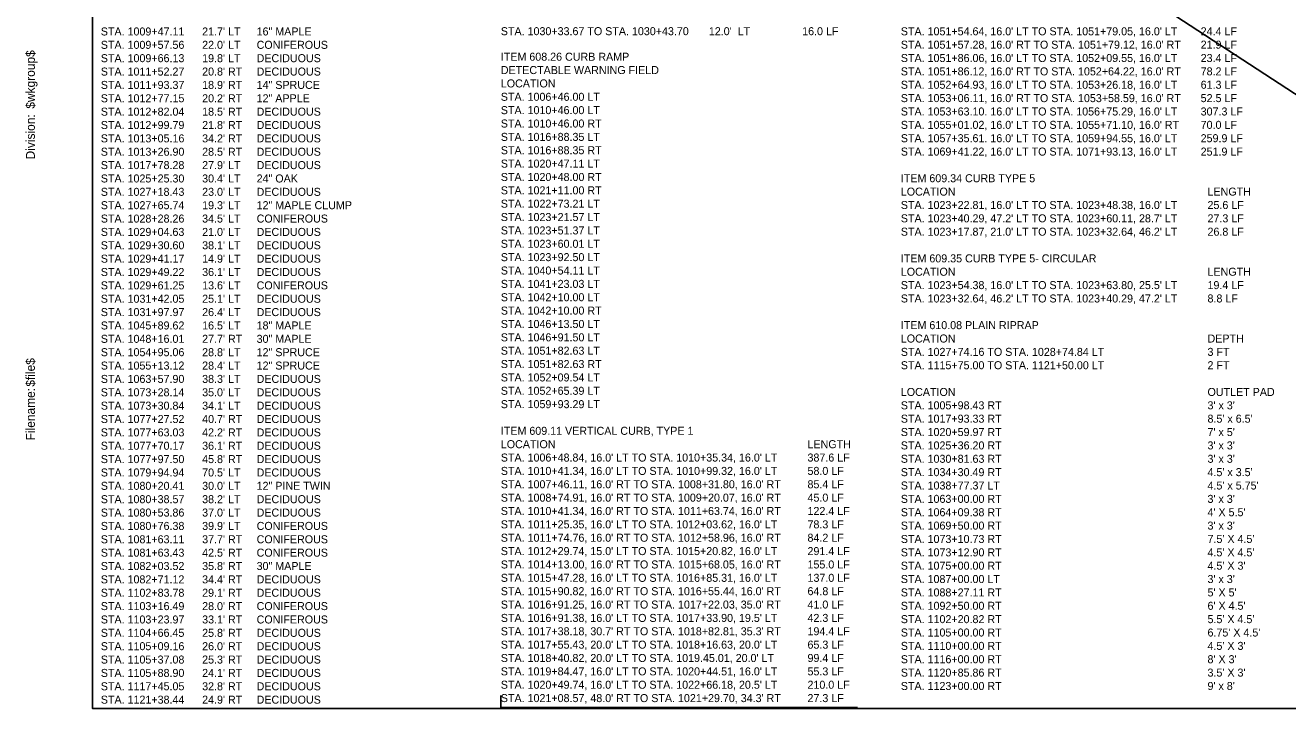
# Model space of a CAD drawing. Extents: x -831 to 3331, y -1004 to 250.
# Drawn here: x 117.9 to 591.3, y -283.3 to -19.2 of the extents above; entities that cross this region are included whole.
import ezdxf

# ---------------------------------------------------------------- set-up
doc = ezdxf.new("R2010")
doc.units = 0
doc.layers.add('BORDER', color=7, linetype='Continuous')
doc.layers.add('Default', color=7, linetype='Continuous')

msp = doc.modelspace()

# ---------------------------------------------------------------- linework, layer by layer
at = {"layer": 'BORDER'}
msp.add_lwpolyline([(143.03, 249.69), (943.03, 249.69), (943.03, -275.31), (143.03, -275.31)], close=True, dxfattribs=at)
at = {"layer": 'Default'}
msp.add_line((143.03, 249.69), (958.96, -283.29), dxfattribs=at)
msp.add_lwpolyline([(296.19, -270.51), (296.19, -274.94), (429.88, -274.94)], dxfattribs=at)

# ---------------------------------------------------------------- texts
at = {"layer": 'BORDER'}
for s, p in [('$wkgroup$', (121.46, -50.46)), ('Division:', (121.46, -69.48)), ('$file$', (121.46, -154.68)), ('Filename:', (121.46, -174.81))]:
    msp.add_text(s, height=3.348, rotation=90, dxfattribs=at).set_placement(p)
at = {"layer": 'Default'}
for s, p in [('STA. 1009+47.11', (146.19, -23.01)), ("21.7' LT", (184.19, -23.01)), ('16" MAPLE', (204.62, -23.01)), ('STA. 1030+33.67 TO STA. 1030+43.70', (296.19, -22.91)), ("12.0'  LT", (374.19, -22.91)), ('16.0 LF', (409.19, -22.91)), ("STA. 1051+54.64, 16.0' LT TO STA. 1051+79.05, 16.0' LT", (446.19, -22.95)), ('24.4 LF', (558.62, -22.95)), ('STA. 1009+57.56', (146.19, -28.02)), ("22.0' LT", (184.19, -28.02)), ('CONIFEROUS', (204.62, -28.02)), ("STA. 1051+57.28, 16.0' RT TO STA. 1051+79.12, 16.0' RT", (446.19, -27.96)), ('21.9 LF', (558.62, -27.96)), ('STA. 1009+66.13', (146.19, -33.03)), ("19.8' LT", (184.19, -33.03)), ('DECIDUOUS', (204.62, -33.03)), ('ITEM 608.26 CURB RAMP ', (296.19, -32.48)), ("STA. 1051+86.06, 16.0' LT TO STA. 1052+09.55, 16.0' LT", (446.19, -32.97)), ('23.4 LF', (558.62, -32.97)), ('STA. 1011+52.27', (146.19, -38.04)), ("20.8' RT", (184.19, -38.04)), ('DECIDUOUS', (204.62, -38.04)), ('DETECTABLE WARNING FIELD', (296.19, -37.48)), ("STA. 1051+86.12, 16.0' RT TO STA. 1052+64.22, 16.0' RT", (446.19, -37.98)), ('78.2 LF', (558.62, -37.98)), ('STA. 1011+93.37', (146.19, -43.05)), ("18.9' RT", (184.19, -43.05)), ('14" SPRUCE', (204.62, -43.05)), ('LOCATION', (296.19, -42.49)), ("STA. 1052+64.93, 16.0' LT TO STA. 1053+26.18, 16.0' LT", (446.19, -42.99)), ('61.3 LF', (558.62, -42.99)), ('STA. 1012+77.15', (146.19, -48.06)), ("20.2' RT", (184.19, -48.06)), ('12" APPLE', (204.62, -48.06)), ('STA. 1006+46.00 LT', (296.19, -47.5)), ("STA. 1053+06.11, 16.0' RT TO STA. 1053+58.59, 16.0' RT", (446.19, -48)), ('52.5 LF', (558.62, -48)), ('STA. 1012+82.04', (146.19, -53.07)), ("18.5' RT", (184.19, -53.07)), ('DECIDUOUS', (204.62, -53.07)), ('STA. 1010+46.00 LT', (296.19, -52.51)), ("STA. 1053+63.10. 16.0' LT TO STA. 1056+75.29, 16.0' LT", (446.19, -53.01)), ('307.3 LF', (558.62, -53.01)), ('STA. 1012+99.79', (146.19, -58.08)), ("21.8' RT", (184.19, -58.08)), ('DECIDUOUS', (204.62, -58.08)), ('STA. 1010+46.00 RT', (296.19, -57.52)), ("STA. 1055+01.02, 16.0' LT TO STA. 1055+71.10, 16.0' RT", (446.19, -58.02)), ('70.0 LF', (558.62, -58.02)), ('STA. 1013+05.16', (146.19, -63.09)), ("34.2' RT", (184.19, -63.09)), ('DECIDUOUS', (204.62, -63.09)), ('STA. 1016+88.35 LT', (296.19, -62.53)), ("STA. 1057+35.61. 16.0' LT TO STA. 1059+94.55, 16.0' LT", (446.19, -63.03)), ('259.9 LF', (558.62, -63.03)), ('STA. 1013+26.90', (146.19, -68.1)), ("28.5' RT", (184.19, -68.1)), ('DECIDUOUS', (204.62, -68.1)), ('STA. 1016+88.35 RT', (296.19, -67.54)), ("STA. 1069+41.22, 16.0' LT TO STA. 1071+93.13, 16.0' LT", (446.19, -68.04)), ('251.9 LF', (558.62, -68.04)), ('STA. 1017+78.28', (146.19, -73.11)), ("27.9' LT", (184.19, -73.11)), ('DECIDUOUS', (204.62, -73.11)), ('STA. 1020+47.11 LT', (296.19, -72.55)), ('STA. 1025+25.30', (146.19, -78.12)), ("30.4' LT", (184.19, -78.12)), ('24" OAK', (204.62, -78.12)), ('STA. 1020+48.00 RT', (296.19, -77.56)), ('ITEM 609.34 CURB TYPE 5', (446.19, -78.04)), ('STA. 1027+18.43', (146.19, -83.13)), ("23.0' LT", (184.19, -83.13)), ('DECIDUOUS', (204.62, -83.13)), ('STA. 1021+11.00 RT', (296.19, -82.57)), ('LOCATION', (446.19, -83.05)), ('LENGTH', (561.19, -83.05)), ('STA. 1027+65.74', (146.19, -88.14)), ("19.3' LT", (184.19, -88.14)), ('12" MAPLE CLUMP', (204.62, -88.14)), ('STA. 1022+73.21 LT', (296.19, -87.58)), ("STA. 1023+22.81, 16.0' LT TO STA. 1023+48.38, 16.0' LT", (446.19, -88.06)), ('25.6 LF', (561.19, -88.06)), ('STA. 1023+21.57 LT', (296.19, -92.59)), ('STA. 1028+28.26', (146.19, -93.15)), ("34.5' LT", (184.19, -93.15)), ('CONIFEROUS', (204.62, -93.15)), ('STA. 1023+51.37 LT', (296.19, -97.6)), ("STA. 1023+40.29, 47.2' LT TO STA. 1023+60.11, 28.7' LT", (446.19, -93.07)), ('27.3 LF', (561.19, -93.07)), ('STA. 1029+04.63', (146.19, -98.16)), ("21.0' LT", (184.19, -98.16)), ('DECIDUOUS', (204.62, -98.16)), ("STA. 1023+17.87, 21.0' LT TO STA. 1023+32.64, 46.2' LT", (446.19, -98.08)), ('26.8 LF', (561.19, -98.08)), ('STA. 1029+30.60', (146.19, -103.17)), ("38.1' LT", (184.19, -103.17)), ('DECIDUOUS', (204.62, -103.17)), ('STA. 1023+60.01 LT', (296.19, -102.61)), ('STA. 1029+41.17', (146.19, -108.18)), ("14.9' LT", (184.19, -108.18)), ('DECIDUOUS', (204.62, -108.18)), ('STA. 1023+92.50 LT', (296.19, -107.62)), ('ITEM 609.35 CURB TYPE 5- CIRCULAR', (446.19, -108.08)), ('STA. 1029+49.22', (146.19, -113.19)), ("36.1' LT", (184.19, -113.19)), ('DECIDUOUS', (204.62, -113.19)), ('STA. 1040+54.11 LT', (296.19, -112.63)), ('LOCATION', (446.19, -113.09)), ('LENGTH', (561.19, -113.09)), ('STA. 1029+61.25', (146.19, -118.2)), ("13.6' LT", (184.19, -118.2)), ('CONIFEROUS', (204.62, -118.2)), ('STA. 1041+23.03 LT', (296.19, -117.64)), ("STA. 1023+54.38, 16.0' LT TO STA. 1023+63.80, 25.5' LT", (446.19, -118.1)), ('19.4 LF', (561.19, -118.1)), ('STA. 1031+42.05', (146.19, -123.21)), ("25.1' LT", (184.19, -123.21)), ('DECIDUOUS', (204.62, -123.21)), ('STA. 1042+10.00 LT', (296.19, -122.65)), ("STA. 1023+32.64, 46.2' LT TO STA. 1023+40.29, 47.2' LT", (446.19, -123.11)), ('8.8 LF', (561.19, -123.11)), ('STA. 1031+97.97', (146.19, -128.22)), ("26.4' LT", (184.19, -128.22)), ('DECIDUOUS', (204.62, -128.22)), ('STA. 1042+10.00 RT', (296.19, -127.66)), ('STA. 1045+89.62', (146.19, -133.23)), ("16.5' LT", (184.19, -133.23)), ('18" MAPLE', (204.62, -133.23)), ('STA. 1046+13.50 LT', (296.19, -132.67)), ('ITEM 610.08 PLAIN RIPRAP', (446.19, -133.11)), ('STA. 1048+16.01', (146.19, -138.24)), ("27.7' RT", (184.19, -138.24)), ('30" MAPLE', (204.62, -138.24)), ('STA. 1046+91.50 LT', (296.19, -137.68)), ('LOCATION', (446.19, -138.12)), ('DEPTH', (561.19, -138.12)), ('STA. 1054+95.06', (146.19, -143.25)), ("28.8' LT", (184.19, -143.25)), ('12" SPRUCE', (204.62, -143.25)), ('STA. 1051+82.63 LT', (296.19, -142.69)), ('STA. 1027+74.16 TO STA. 1028+74.84 LT', (446.19, -143.13)), ('3 FT', (561.19, -143.13)), ('STA. 1055+13.12', (146.19, -148.26)), ("28.4' LT", (184.19, -148.26)), ('12" SPRUCE', (204.62, -148.26)), ('STA. 1051+82.63 RT', (296.19, -147.7)), ('STA. 1115+75.00 TO STA. 1121+50.00 LT', (446.19, -148.14)), ('2 FT', (561.19, -148.14)), ('STA. 1063+57.90', (146.19, -153.27)), ("38.3' LT", (184.19, -153.27)), ('DECIDUOUS', (204.62, -153.27)), ('STA. 1052+09.54 LT', (296.19, -152.71)), ('STA. 1073+28.14', (146.19, -158.28)), ("35.0' LT", (184.19, -158.28)), ('DECIDUOUS', (204.62, -158.28)), ('STA. 1052+65.39 LT', (296.19, -157.72)), ('LOCATION', (446.19, -158.16)), ('OUTLET PAD', (561.19, -158.16)), ('STA. 1073+30.84', (146.19, -163.29)), ("34.1' LT", (184.19, -163.29)), ('DECIDUOUS', (204.62, -163.29)), ('STA. 1059+93.29 LT', (296.19, -162.73)), ('STA. 1005+98.43 RT', (446.19, -163.17)), ("3' x 3'", (561.19, -163.17)), ('STA. 1077+27.52', (146.19, -168.3)), ("40.7' RT", (184.19, -168.3)), ('DECIDUOUS', (204.62, -168.3)), ('STA. 1017+93.33 RT', (446.19, -168.18)), ("8.5' x 6.5'", (561.19, -168.18)), ('STA. 1077+63.03', (146.19, -173.31)), ("42.2' RT", (184.19, -173.31)), ('DECIDUOUS', (204.62, -173.31)), ('ITEM 609.11 VERTICAL CURB, TYPE 1', (296.19, -172.73)), ('STA. 1020+59.97 RT', (446.19, -173.19)), ("7' x 5'", (561.19, -173.19)), ('LOCATION', (296.19, -177.74)), ('LENGTH', (411.19, -177.74)), ('STA. 1025+36.20 RT', (446.19, -178.2)), ("3' x 3'", (561.19, -178.2)), ('STA. 1077+70.17', (146.19, -178.32)), ("36.1' RT", (184.19, -178.32)), ('DECIDUOUS', (204.62, -178.32)), ("STA. 1006+48.84, 16.0' LT TO STA. 1010+35.34, 16.0' LT", (296.19, -182.75)), ('387.6 LF', (411.19, -182.75)), ('STA. 1077+97.50', (146.19, -183.33)), ("45.8' RT", (184.19, -183.33)), ('DECIDUOUS', (204.62, -183.33)), ('STA. 1030+81.63 RT', (446.19, -183.21)), ("3' x 3'", (561.19, -183.21)), ('STA. 1079+94.94', (146.19, -188.34)), ("70.5' LT", (184.19, -188.34)), ('DECIDUOUS', (204.62, -188.34)), ("STA. 1010+41.34, 16.0' LT TO STA. 1010+99.32, 16.0' LT", (296.19, -187.76)), ('58.0 LF', (411.19, -187.76)), ('STA. 1034+30.49 RT', (446.19, -188.22)), ("4.5' x 3.5'", (561.19, -188.22)), ('STA. 1080+20.41', (146.19, -193.35)), ("30.0' LT", (184.19, -193.35)), ('12" PINE TWIN', (204.62, -193.35)), ("STA. 1007+46.11, 16.0' RT TO STA. 1008+31.80, 16.0' RT", (296.19, -192.77)), ('85.4 LF', (411.19, -192.77)), ('STA. 1038+77.37 LT', (446.19, -193.23)), ("4.5' x 5.75'", (561.19, -193.23)), ('STA. 1080+38.57', (146.19, -198.36)), ("38.2' LT", (184.19, -198.36)), ('DECIDUOUS', (204.62, -198.36)), ("STA. 1008+74.91, 16.0' RT TO STA. 1009+20.07, 16.0' RT", (296.19, -197.78)), ('45.0 LF', (411.19, -197.78)), ('STA. 1063+00.00 RT', (446.19, -198.24)), ("3' x 3'", (561.19, -198.24)), ('STA. 1080+53.86', (146.19, -203.37)), ("37.0' LT", (184.19, -203.37)), ('DECIDUOUS', (204.62, -203.37)), ("STA. 1010+41.34, 16.0' RT TO STA. 1011+63.74, 16.0' RT", (296.19, -202.79)), ('122.4 LF', (411.19, -202.79)), ('STA. 1064+09.38 RT', (446.19, -203.25)), ("4' X 5.5'", (561.19, -203.25)), ('STA. 1080+76.38', (146.19, -208.38)), ("39.9' LT", (184.19, -208.38)), ('CONIFEROUS', (204.62, -208.38)), ("STA. 1011+25.35, 16.0' LT TO STA. 1012+03.62, 16.0' LT ", (296.19, -207.8)), ('78.3 LF', (411.19, -207.8)), ('STA. 1069+50.00 RT', (446.19, -208.26)), ("3' x 3'", (561.19, -208.26)), ('STA. 1081+63.11', (146.19, -213.39)), ("37.7' RT", (184.19, -213.39)), ('CONIFEROUS', (204.62, -213.39)), ("STA. 1011+74.76, 16.0' RT TO STA. 1012+58.96, 16.0' RT", (296.19, -212.81)), ('84.2 LF', (411.19, -212.81)), ('STA. 1073+10.73 RT', (446.19, -213.27)), ("7.5' X 4.5'", (561.19, -213.27)), ('STA. 1081+63.43', (146.19, -218.4)), ("42.5' RT", (184.19, -218.4)), ('CONIFEROUS', (204.62, -218.4)), ("STA. 1012+29.74, 15.0' LT TO STA. 1015+20.82, 16.0' LT", (296.19, -217.82)), ('291.4 LF', (411.19, -217.82)), ('STA. 1073+12.90 RT', (446.19, -218.28)), ("4.5' X 4.5'", (561.19, -218.28)), ('STA. 1082+03.52', (146.19, -223.41)), ("35.8' RT", (184.19, -223.41)), ('30" MAPLE', (204.62, -223.41)), ("STA. 1014+13.00, 16.0' RT TO STA. 1015+68.05, 16.0' RT", (296.19, -222.83)), ('155.0 LF', (411.19, -222.83)), ('STA. 1075+00.00 RT', (446.19, -223.29)), ("4.5' X 3'", (561.19, -223.29)), ('STA. 1082+71.12', (146.19, -228.42)), ("34.4' RT", (184.19, -228.42)), ('DECIDUOUS', (204.62, -228.42)), ("STA. 1015+47.28, 16.0' LT TO STA. 1016+85.31, 16.0' LT", (296.19, -227.84)), ('137.0 LF', (411.19, -227.84)), ('STA. 1087+00.00 LT', (446.19, -228.3)), ("3' x 3'", (561.19, -228.3)), ('STA. 1102+83.78', (146.19, -233.43)), ("29.1' RT", (184.19, -233.43)), ('DECIDUOUS', (204.62, -233.43)), ("STA. 1015+90.82, 16.0' RT TO STA. 1016+55.44, 16.0' RT", (296.19, -232.85)), ('64.8 LF', (411.19, -232.85)), ('STA. 1088+27.11 RT', (446.19, -233.31)), ("5' X 5'", (561.19, -233.31)), ('STA. 1103+16.49', (146.19, -238.44)), ("28.0' RT", (184.19, -238.44)), ('CONIFEROUS', (204.62, -238.44)), ("STA. 1016+91.25, 16.0' RT TO STA. 1017+22.03, 35.0' RT", (296.19, -237.86)), ('41.0 LF', (411.19, -237.86)), ('STA. 1092+50.00 RT', (446.19, -238.32)), ("6' X 4.5'", (561.19, -238.32)), ('STA. 1103+23.97', (146.19, -243.45)), ("33.1' RT", (184.19, -243.45)), ('CONIFEROUS', (204.62, -243.45)), ("STA. 1016+91.38, 16.0' LT TO STA. 1017+33.90, 19.5' LT", (296.19, -242.87)), ('42.3 LF', (411.19, -242.87)), ('STA. 1102+20.82 RT', (446.19, -243.33)), ("5.5' X 4.5'", (561.19, -243.33)), ('STA. 1104+66.45', (146.19, -248.46)), ("25.8' RT", (184.19, -248.46)), ('DECIDUOUS', (204.62, -248.46)), ("STA. 1017+38.18, 30.7' RT TO STA. 1018+82.81, 35.3' RT", (296.19, -247.88)), ('194.4 LF', (411.19, -247.88)), ('STA. 1105+00.00 RT', (446.19, -248.34)), ("6.75' X 4.5'", (561.19, -248.34)), ('STA. 1105+09.16', (146.19, -253.47)), ("26.0' RT", (184.19, -253.47)), ('DECIDUOUS', (204.62, -253.47)), ("STA. 1017+55.43, 20.0' LT TO STA. 1018+16.63, 20.0' LT", (296.19, -252.89)), ('65.3 LF', (411.19, -252.89)), ('STA. 1110+00.00 RT', (446.19, -253.35)), ("4.5' X 3'", (561.19, -253.35)), ('STA. 1105+37.08', (146.19, -258.48)), ("25.3' RT", (184.19, -258.48)), ('DECIDUOUS', (204.62, -258.48)), ("STA. 1018+40.82, 20.0' LT TO STA. 1019.45.01, 20.0' LT", (296.19, -257.9)), ('99.4 LF', (411.19, -257.9)), ('STA. 1116+00.00 RT', (446.19, -258.36)), ("8' X 3'", (561.19, -258.36)), ("STA. 1019+84.47, 16.0' LT TO STA. 1020+44.51, 16.0' LT", (296.19, -262.91)), ('55.3 LF', (411.19, -262.91)), ('STA. 1120+85.86 RT', (446.19, -263.37)), ("3.5' X 3'", (561.19, -263.37)), ('STA. 1105+88.90', (146.19, -263.49)), ("24.1' RT", (184.19, -263.49)), ('DECIDUOUS', (204.62, -263.49)), ("STA. 1020+49.74, 16.0' LT TO STA. 1022+66.18, 20.5' LT", (296.19, -267.92)), ('210.0 LF', (411.19, -267.92)), ('STA. 1117+45.05', (146.19, -268.5)), ("32.8' RT", (184.19, -268.5)), ('DECIDUOUS', (204.62, -268.5)), ('STA. 1123+00.00 RT', (446.19, -268.38)), ("9' x 8'", (561.19, -268.38)), ('STA. 1121+38.44', (146.19, -273.51)), ("24.9' RT", (184.19, -273.51)), ('DECIDUOUS', (204.62, -273.51)), ("STA. 1021+08.57, 48.0' RT TO STA. 1021+29.70, 34.3' RT", (296.19, -272.93)), ('27.3 LF', (411.19, -272.93))]:
    msp.add_text(s, height=3, dxfattribs=at).set_placement(p)

doc.saveas('drawing.dxf')
